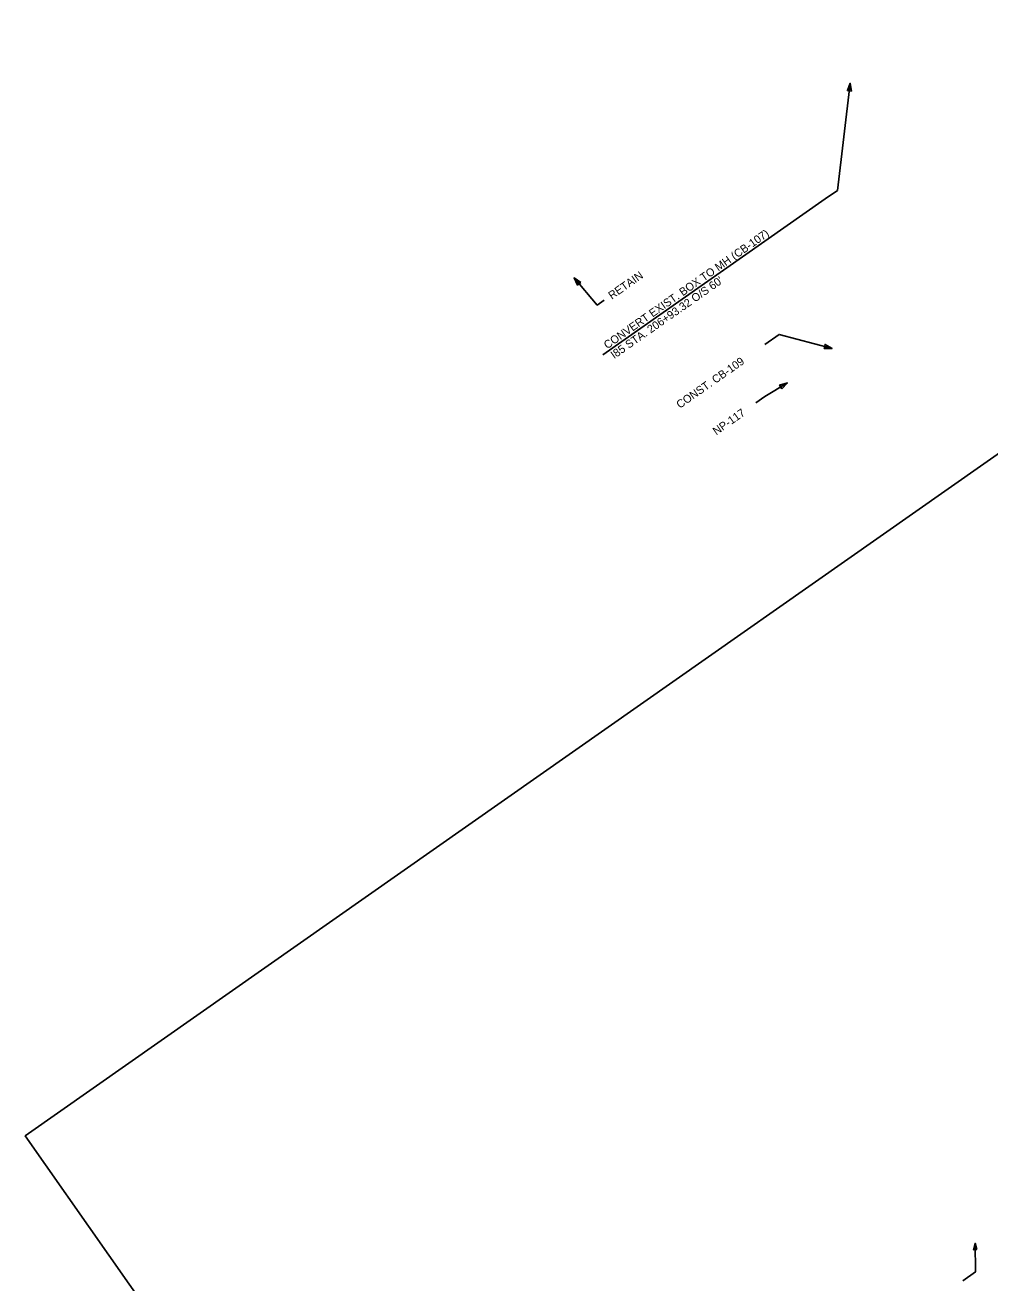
# Model space of a CAD drawing. Extents: x 1603736 to 1605697, y 1088463 to 1090389.
# Drawn here: x 1603817 to 1604540, y 1089408 to 1090350 of the extents above; entities that cross this region are included whole.
import ezdxf

# ---------------------------------------------------------------- set-up
doc = ezdxf.new("R2010")
doc.units = 0
doc.layers.add('Plan_Clip', color=7, linetype='Continuous')
doc.layers.add('RD_TX_Drainage', color=7, linetype='Continuous')

msp = doc.modelspace()

# ---------------------------------------------------------------- linework, layer by layer
at = {"layer": 'Plan_Clip'}
msp.add_lwpolyline([(1605233.56, 1090111.04), (1605405.83, 1089865.44), (1605593.12, 1089598.42), (1604362.43, 1088735.18), (1604177.81, 1089004.07), (1604005.53, 1089249.68), (1603817.48, 1089517.78), (1604919.05, 1090290.45), (1604939.78, 1090260.89), (1605067.39, 1090350.4)], close=True, dxfattribs=at)
msp.add_lwpolyline([(1605233.56, 1090111.04), (1605405.83, 1089865.44), (1605593.12, 1089598.42), (1604362.43, 1088735.18), (1604177.81, 1089004.07), (1604005.53, 1089249.68), (1603817.48, 1089517.78), (1604919.05, 1090290.45), (1604939.78, 1090260.89), (1605067.39, 1090350.4)], close=True, dxfattribs=at)
msp.add_lwpolyline([(1605233.56, 1090111.04), (1605405.83, 1089865.44), (1605593.12, 1089598.42), (1604362.43, 1088735.18), (1604177.81, 1089004.07), (1604005.53, 1089249.68), (1603817.48, 1089517.78), (1604919.05, 1090290.45), (1604939.78, 1090260.89), (1605067.39, 1090350.4)], close=True, dxfattribs=at)
msp.add_lwpolyline([(1605233.56, 1090111.04), (1605405.83, 1089865.44), (1605593.12, 1089598.42), (1604362.43, 1088735.18), (1604177.81, 1089004.07), (1604005.53, 1089249.68), (1603817.48, 1089517.78), (1604919.05, 1090290.45), (1604939.78, 1090260.89), (1605067.39, 1090350.4)], close=True, dxfattribs=at)
msp.add_lwpolyline([(1605233.56, 1090111.04), (1605405.83, 1089865.44), (1605593.12, 1089598.42), (1604362.43, 1088735.18), (1604177.81, 1089004.07), (1604005.53, 1089249.68), (1603817.48, 1089517.78), (1604919.05, 1090290.45), (1604939.78, 1090260.89), (1605067.39, 1090350.4)], close=True, dxfattribs=at)
msp.add_lwpolyline([(1605233.56, 1090111.04), (1605405.83, 1089865.44), (1605593.12, 1089598.42), (1604362.43, 1088735.18), (1604177.81, 1089004.07), (1604005.53, 1089249.68), (1603817.48, 1089517.78), (1604919.05, 1090290.45), (1604939.78, 1090260.89), (1605067.39, 1090350.4)], close=True, dxfattribs=at)
msp.add_lwpolyline([(1605233.56, 1090111.04), (1605405.83, 1089865.44), (1605593.12, 1089598.42), (1604362.43, 1088735.18), (1604177.81, 1089004.07), (1604005.53, 1089249.68), (1603817.48, 1089517.78), (1604919.05, 1090290.45), (1604939.78, 1090260.89), (1605067.39, 1090350.4)], close=True, dxfattribs=at)
msp.add_lwpolyline([(1605233.56, 1090111.04), (1605405.83, 1089865.44), (1605593.12, 1089598.42), (1604362.43, 1088735.18), (1604177.81, 1089004.07), (1604005.53, 1089249.68), (1603817.48, 1089517.78), (1604919.05, 1090290.45), (1604939.78, 1090260.89), (1605067.39, 1090350.4)], close=True, dxfattribs=at)
at = {"layer": 'RD_TX_Drainage'}
msp.add_line((1604416.91, 1090220.13), (1604250.33, 1090103.29), dxfattribs=at)
for points in [[(1604416.91, 1090220.13), (1604425.95, 1090226.47), (1604435.66, 1090306.87)], [(1604251.18, 1090144.15), (1604246.11, 1090140.59), (1604228.69, 1090160.93)], [(1604371.68, 1090111.15), (1604382.34, 1090118.63), (1604421.95, 1090108.1)], [(1604364.83, 1090067.29), (1604371.53, 1090071.99), (1604388.48, 1090082.26)], [(1604519.88, 1089409.27), (1604529.38, 1089415.93), (1604529.07, 1089437.42)]]:
    msp.add_lwpolyline(points, dxfattribs=at)
for points in [[(1604436.51, 1090300.93), (1604435.66, 1090306.87), (1604433.42, 1090301.3)], [(1604233.64, 1090157.54), (1604228.69, 1090160.93), (1604231.28, 1090155.52)], [(1604415.95, 1090108.09), (1604421.95, 1090108.1), (1604416.74, 1090111.09)], [(1604384.33, 1090077.93), (1604388.48, 1090082.26), (1604382.72, 1090080.59)], [(1604530.43, 1089432.61), (1604529.07, 1089437.42), (1604527.85, 1089432.57)]]:
    msp.add_lwpolyline(points, close=True, dxfattribs=at)

# ---------------------------------------------------------------- texts
for s, p in [('CONVERT EXIST. BOX TO MH (CB-107)', (1604253.57, 1090107.39)), ('RETAIN', (1604256.99, 1090144.56)), ("I85 STA. 206+93.32 O/S 60'", (1604258.73, 1090100.02)), ('CONST. CB-109', (1604307.96, 1090062.79)), ('NP-117', (1604335.23, 1090042.86))]:
    msp.add_text(s, height=6, rotation=35.04683, dxfattribs=at).set_placement(p)

doc.saveas('drawing.dxf')
